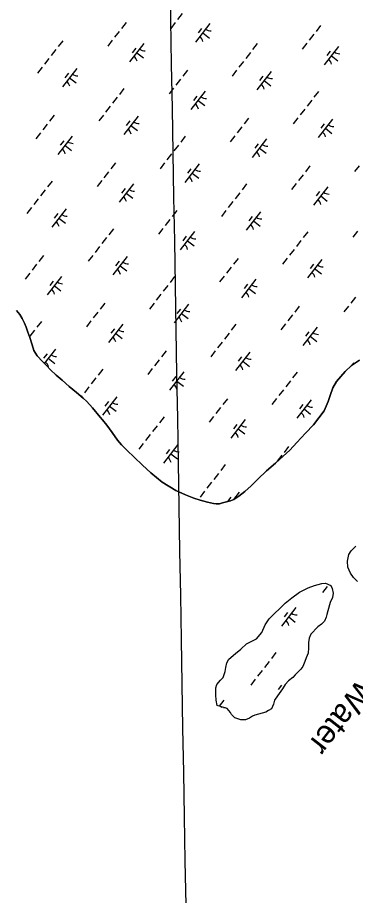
# Model space of a CAD drawing. Extents: x 3888273 to 3909528, y 158682 to 181032.
# Drawn here: x 3904160 to 3904884, y 170026 to 171905 of the extents above; entities that cross this region are included whole.
import ezdxf

# ---------------------------------------------------------------- set-up
doc = ezdxf.new("R2010")
doc.units = 0
for name, color, linetype in [('V-GRID-MAJR', 7, 'Continuous'), ('V-RIVR-IDEN', 7, 'Continuous'), ('V-TOPO-SHOR', 7, 'Continuous'), ('V-WETL-SWMP', 7, 'Continuous')]:
    doc.layers.add(name, color=color, linetype=linetype)

msp = doc.modelspace()

# ---------------------------------------------------------------- linework, layer by layer
at = {"layer": 'V-GRID-MAJR'}
msp.add_spline([(3904558.1, 167799.4), (3904538.3, 168964), (3904435.1, 175024.2), (3904428.3, 175428.5)], degree=3, dxfattribs=at)
at = {"layer": 'V-TOPO-SHOR'}
for points in [[(3904157.7, 171277.9), (3904164.6, 171269.2), (3904169.4, 171261), (3904174.7, 171250.7), (3904178, 171242.4), (3904181.7, 171231.3), (3904185.7, 171219.8), (3904190.7, 171204.8), (3904194.8, 171192.1), (3904202, 171181.1), (3904212.9, 171168.9), (3904222.1, 171159.4), (3904230.2, 171151.2), (3904242.6, 171139.8)], [(3904242.6, 171139.8), (3904255.4, 171128.8), (3904270.3, 171115.4), (3904285.9, 171102.5), (3904299.9, 171090.3), (3904307.9, 171082.9), (3904320, 171069.5), (3904336.9, 171049.8), (3904341.7, 171043.9), (3904350.6, 171032.9), (3904362.3, 171017.1), (3904373.6, 171000.5), (3904382.4, 170990.7), (3904394.8, 170978.1), (3904409.7, 170964), (3904427, 170947.1), (3904445.4, 170930.6), (3904469.8, 170911), (3904498.6, 170892.6), (3904519.4, 170883.7), (3904537.3, 170876.7), (3904550.5, 170872.1), (3904566.4, 170867.9), (3904579.2, 170864.8), (3904585.1, 170864.1), (3904592.3, 170864.6), (3904598.6, 170866.2), (3904607.3, 170868.7), (3904615.6, 170870.8), (3904623.2, 170873.6), (3904633.4, 170880.5), (3904646.4, 170890.6), (3904660.2, 170902.6), (3904674.7, 170917.1), (3904692.8, 170934.8), (3904712.1, 170951.6), (3904728.7, 170966.1), (3904742.8, 170979), (3904757.7, 170995.4), (3904776.6, 171015.5), (3904793.5, 171033.5), (3904805.3, 171048), (3904816.2, 171063.2), (3904825.1, 171083.5), (3904829.4, 171095.9), (3904834.8, 171112.6), (3904843, 171126.2), (3904861.4, 171147.1), (3904875.2, 171160.3), (3904892.1, 171172)], [(3904887.6, 170698.3), (3904879.2, 170707), (3904872.7, 170716), (3904867.1, 170729), (3904866.5, 170741.7), (3904869.6, 170755.6), (3904874.6, 170763.5), (3904884, 170773.9)], [(3904829.1, 170652.9), (3904824.5, 170635.2), (3904822.2, 170627.5), (3904820.8, 170621.8), (3904817.1, 170613.6), (3904810.4, 170606.8), (3904802.9, 170601), (3904787.7, 170585.6), (3904784, 170577), (3904782.7, 170567.9), (3904782.7, 170561.2), (3904782.8, 170556.4), (3904782, 170544.9), (3904778.2, 170534.9), (3904775, 170527.2), (3904770.8, 170516.6), (3904766.6, 170510.9), (3904762.3, 170506.1), (3904754.7, 170498.3), (3904749.1, 170493), (3904740.1, 170485.3), (3904733, 170478), (3904726.9, 170468.4), (3904716.5, 170453.5), (3904710.4, 170443.9), (3904708.1, 170435.8), (3904703.5, 170425.7), (3904697.3, 170421.8), (3904691.6, 170418.4), (3904683.5, 170416.4), (3904675.9, 170414.4), (3904668.3, 170411.9), (3904663, 170410), (3904656.4, 170405.6), (3904648.3, 170402.2), (3904637.8, 170402.1), (3904633.5, 170403.5), (3904625.3, 170406.7), (3904618.1, 170413.3), (3904616.1, 170417.6), (3904608.4, 170426.6), (3904596.4, 170429.8), (3904587.3, 170432.6), (3904585.3, 170444), (3904584.7, 170456), (3904584.1, 170470.8), (3904586.4, 170477.5), (3904594.4, 170487.1), (3904600.1, 170492.9), (3904604.7, 170505.4), (3904605.6, 170514), (3904607.9, 170524), (3904612.1, 170532.2), (3904626.8, 170544.3), (3904638.1, 170553.5), (3904649.9, 170565), (3904661.3, 170570.4), (3904671.8, 170575.8), (3904683.1, 170588.8), (3904690.1, 170605.1), (3904699, 170618.6), (3904733.1, 170651.9), (3904747.3, 170663), (3904763.4, 170675.1), (3904782.4, 170684.9), (3904795.7, 170689.8), (3904811.4, 170693.8), (3904819.6, 170694.3), (3904831.1, 170689.7), (3904833.5, 170683.5), (3904836, 170673), (3904834.2, 170663.9), (3904829.1, 170652.9)]]:
    msp.add_lwpolyline(points, dxfattribs=at)
at = {"layer": 'V-WETL-SWMP'}
for p, q in [((3904512.4, 171913.1), (3904502.5, 171900.5)), ((3904392.2, 171893.9), (3904382.3, 171881.3)), ((3904497.6, 171894.2), (3904487.8, 171881.5)), ((3904377.4, 171875), (3904367.6, 171862.4)), ((3904571.8, 171891.7), (3904541.1, 171852.2)), ((3904554, 171881.4), (3904546.6, 171872)), ((3904808.8, 171887.7), (3904799, 171875.1)), ((3904256.4, 171855.1), (3904246.6, 171842.4)), ((3904362.7, 171856), (3904352.9, 171843.4)), ((3904556.4, 171872), (3904570.6, 171860.9)), ((3904794.1, 171868.8), (3904784.3, 171856.1)), ((3904241.7, 171836.1), (3904231.9, 171823.5)), ((3904430.5, 171849.2), (3904399.8, 171809.8)), ((3904412.8, 171839), (3904405.4, 171829.5)), ((3904673.1, 171848.8), (3904663.3, 171836.2)), ((3904779.3, 171849.8), (3904769.5, 171837.2)), ((3904847.2, 171843), (3904816.5, 171803.6)), ((3904227, 171817.2), (3904217.1, 171804.6)), ((3904415.2, 171829.5), (3904429.4, 171818.5)), ((3904658.4, 171829.9), (3904648.6, 171817.3)), ((3904829.4, 171832.8), (3904822.1, 171823.3)), ((3904831.8, 171823.3), (3904846, 171812.2)), ((3904643.6, 171811), (3904633.8, 171798.3)), ((3904212.2, 171798.2), (3904202.4, 171785.6)), ((3904286.4, 171795.8), (3904255.7, 171756.3)), ((3904268.6, 171785.5), (3904261.2, 171776)), ((3904523.4, 171791.8), (3904513.6, 171779.1)), ((3904628.9, 171792), (3904619.1, 171779.4)), ((3904703, 171789.5), (3904672.3, 171750.1)), ((3904271, 171776), (3904285.2, 171765)), ((3904508.7, 171772.8), (3904498.9, 171760.2)), ((3904685.3, 171779.3), (3904677.9, 171769.8)), ((3904687.7, 171769.8), (3904701.9, 171758.8)), ((3904387.7, 171752.9), (3904377.9, 171740.3)), ((3904494, 171753.9), (3904484.1, 171741.3)), ((3904561.8, 171747.1), (3904531.1, 171707.6)), ((3904804.4, 171746.7), (3904794.6, 171734.1)), ((3904373, 171734), (3904363.2, 171721.4)), ((3904544, 171736.8), (3904536.7, 171727.4)), ((3904546.4, 171727.4), (3904560.7, 171716.3)), ((3904789.7, 171727.8), (3904779.8, 171715.1)), ((3904358.3, 171715), (3904348.4, 171702.4)), ((3904774.9, 171708.8), (3904765.1, 171696.2)), ((3904238.1, 171695.9), (3904228.2, 171683.2)), ((3904343.5, 171696.1), (3904333.7, 171683.5)), ((3904417.7, 171693.6), (3904387, 171654.2)), ((3904654.7, 171689.6), (3904644.9, 171677)), ((3904760.2, 171689.9), (3904750.4, 171677.2)), ((3904834.3, 171687.4), (3904803.6, 171647.9)), ((3904223.3, 171676.9), (3904213.5, 171664.3)), ((3904399.9, 171683.4), (3904392.5, 171673.9)), ((3904402.3, 171673.9), (3904416.5, 171662.8)), ((3904640, 171670.7), (3904630.2, 171658.1)), ((3904816.6, 171677.1), (3904809.2, 171667.7)), ((3904819, 171667.7), (3904833.2, 171656.6)), ((3904208.6, 171658), (3904198.7, 171645.3)), ((3904276.4, 171651.2), (3904245.7, 171611.7)), ((3904519, 171650.8), (3904509.2, 171638.2)), ((3904625.2, 171651.7), (3904615.4, 171639.1)), ((3904258.7, 171640.9), (3904251.3, 171631.5)), ((3904261.1, 171631.4), (3904275.3, 171620.4)), ((3904504.3, 171631.8), (3904494.4, 171619.2)), ((3904693.1, 171645), (3904662.4, 171605.5)), ((3904675.3, 171634.7), (3904668, 171625.2)), ((3904489.5, 171612.9), (3904479.7, 171600.3)), ((3904677.7, 171625.2), (3904691.9, 171614.2)), ((3904369.3, 171593.7), (3904359.5, 171581.1)), ((3904474.8, 171594), (3904465, 171581.3)), ((3904354.6, 171574.8), (3904344.8, 171562.1)), ((3904548.9, 171591.5), (3904518.2, 171552)), ((3904531.2, 171581.2), (3904523.8, 171571.8)), ((3904786, 171587.5), (3904776.2, 171574.9)), ((3904891.5, 171587.7), (3904881.6, 171575.1)), ((3904233.6, 171554.9), (3904223.8, 171542.2)), ((3904339.9, 171555.8), (3904330, 171543.2)), ((3904533.6, 171571.8), (3904547.8, 171560.7)), ((3904771.3, 171568.5), (3904761.4, 171555.9)), ((3904218.9, 171535.9), (3904209.1, 171523.3)), ((3904407.7, 171549), (3904377, 171509.6)), ((3904389.9, 171538.8), (3904382.6, 171529.3)), ((3904650.3, 171548.6), (3904640.5, 171536)), ((3904756.5, 171549.6), (3904746.7, 171537)), ((3904824.4, 171542.8), (3904793.7, 171503.3)), ((3904204.1, 171517), (3904194.3, 171504.4)), ((3904392.3, 171529.3), (3904406.5, 171518.2)), ((3904635.6, 171529.7), (3904625.7, 171517.1)), ((3904806.6, 171532.6), (3904799.2, 171523.1)), ((3904809, 171523.1), (3904823.2, 171512)), ((3904189.4, 171498), (3904179.6, 171485.4)), ((3904620.8, 171510.8), (3904611, 171498.1)), ((3904263.5, 171495.6), (3904232.8, 171456.1)), ((3904245.8, 171485.3), (3904238.4, 171475.8)), ((3904500.6, 171491.6), (3904490.8, 171478.9)), ((3904606.1, 171491.8), (3904596.2, 171479.2)), ((3904680.2, 171489.3), (3904649.5, 171449.9)), ((3904248.2, 171475.8), (3904262.4, 171464.8)), ((3904485.9, 171472.6), (3904476, 171460)), ((3904662.5, 171479.1), (3904655.1, 171469.6)), ((3904664.9, 171469.6), (3904679.1, 171458.6)), ((3904364.9, 171452.7), (3904355.1, 171440.1)), ((3904471.1, 171453.7), (3904461.3, 171441.1)), ((3904539, 171446.9), (3904508.3, 171407.4)), ((3904781.6, 171446.5), (3904771.7, 171433.9)), ((3904887.8, 171447.5), (3904878, 171434.8)), ((3904350.2, 171433.8), (3904340.3, 171421.1)), ((3904521.2, 171436.6), (3904513.9, 171427.2)), ((3904523.6, 171427.2), (3904537.8, 171416.1)), ((3904766.8, 171427.6), (3904757, 171414.9)), ((3904335.4, 171414.8), (3904325.6, 171402.2)), ((3904752.1, 171408.6), (3904742.3, 171396)), ((3904215.2, 171395.7), (3904205.4, 171383)), ((3904320.7, 171395.9), (3904310.9, 171383.3)), ((3904394.8, 171393.4), (3904364.1, 171354)), ((3904631.9, 171389.4), (3904622.1, 171376.8)), ((3904737.4, 171389.7), (3904727.5, 171377)), ((3904811.5, 171387.2), (3904780.8, 171347.7)), ((3904200.5, 171376.7), (3904190.7, 171364.1)), ((3904377.1, 171383.2), (3904369.7, 171373.7)), ((3904379.5, 171373.7), (3904393.7, 171362.6)), ((3904617.2, 171370.5), (3904607.3, 171357.9)), ((3904793.7, 171376.9), (3904786.4, 171367.5)), ((3904796.1, 171367.5), (3904810.4, 171356.4)), ((3904185.7, 171357.8), (3904175.9, 171345.1)), ((3904253.6, 171351), (3904222.9, 171311.5)), ((3904496.2, 171350.6), (3904486.4, 171337.9)), ((3904602.4, 171351.5), (3904592.6, 171338.9)), ((3904235.8, 171340.7), (3904228.5, 171331.2)), ((3904238.2, 171331.2), (3904252.4, 171320.2)), ((3904481.4, 171331.6), (3904471.6, 171319)), ((3904670.3, 171344.7), (3904639.6, 171305.3)), ((3904652.5, 171334.5), (3904645.1, 171325)), ((3904466.7, 171312.7), (3904456.9, 171300.1)), ((3904654.9, 171325), (3904669.1, 171314)), ((3904346.5, 171293.5), (3904336.7, 171280.9)), ((3904452, 171293.7), (3904442.1, 171281.1)), ((3904883.4, 171306.5), (3904873.5, 171293.8)), ((3904164.6, 171269.2), (3904157.7, 171277.9)), ((3904331.8, 171274.6), (3904321.9, 171261.9)), ((3904526.1, 171291.3), (3904495.4, 171251.8)), ((3904508.4, 171281), (3904501, 171271.5)), ((3904763.2, 171287.3), (3904753.3, 171274.7)), ((3904868.6, 171287.5), (3904858.8, 171274.9)), ((3904169.4, 171261), (3904164.6, 171269.2)), ((3904174.7, 171250.7), (3904169.4, 171261)), ((3904210.8, 171254.7), (3904201, 171242)), ((3904317, 171255.6), (3904307.2, 171243)), ((3904510.8, 171271.5), (3904525, 171260.5)), ((3904748.4, 171268.3), (3904738.6, 171255.7)), ((3904178, 171242.4), (3904174.7, 171250.7)), ((3904181.7, 171231.3), (3904178, 171242.4)), ((3904196.1, 171235.7), (3904186.2, 171223.1)), ((3904384.9, 171248.8), (3904354.2, 171209.4)), ((3904367.1, 171238.6), (3904359.7, 171229.1)), ((3904627.5, 171248.4), (3904617.6, 171235.8)), ((3904733.7, 171249.4), (3904723.9, 171236.8)), ((3904801.5, 171242.6), (3904770.8, 171203.1)), ((3904185.7, 171219.8), (3904181.7, 171231.3)), ((3904190.7, 171204.8), (3904185.7, 171219.8)), ((3904369.5, 171229.1), (3904383.7, 171218)), ((3904612.7, 171229.5), (3904602.9, 171216.9)), ((3904783.8, 171232.3), (3904776.4, 171222.9)), ((3904786.2, 171222.9), (3904800.4, 171211.8)), ((3904194.8, 171192.1), (3904190.7, 171204.8)), ((3904598, 171210.5), (3904588.2, 171197.9)), ((3904202, 171181.1), (3904194.8, 171192.1)), ((3904212.9, 171168.9), (3904202, 171181.1)), ((3904223, 171185.1), (3904215.6, 171175.6)), ((3904240.7, 171195.4), (3904216.9, 171164.8)), ((3904477.8, 171191.4), (3904468, 171178.7)), ((3904583.2, 171191.6), (3904573.4, 171179)), ((3904657.4, 171189.1), (3904626.7, 171149.7)), ((3904639.6, 171178.9), (3904632.3, 171169.4)), ((3904222.1, 171159.4), (3904212.9, 171168.9)), ((3904225.4, 171175.6), (3904239.6, 171164.6)), ((3904463, 171172.4), (3904453.2, 171159.8)), ((3904642, 171169.4), (3904656.2, 171158.3)), ((3904875.2, 171160.3), (3904861.4, 171147.1)), ((3904879.7, 171166.2), (3904875, 171160.1)), ((3904892.1, 171172), (3904875.2, 171160.3)), ((3904230.2, 171151.2), (3904222.1, 171159.4)), ((3904242.6, 171139.8), (3904230.2, 171151.2)), ((3904342.1, 171152.5), (3904332.3, 171139.9)), ((3904448.3, 171153.5), (3904438.5, 171140.8)), ((3904516.2, 171146.7), (3904485.4, 171107.2)), ((3904758.7, 171146.3), (3904748.9, 171133.7)), ((3904861.4, 171147.1), (3904843, 171126.2)), ((3904255.4, 171128.8), (3904242.6, 171139.8)), ((3904270.3, 171115.4), (3904255.4, 171128.8)), ((3904327.3, 171133.6), (3904317.5, 171120.9)), ((3904498.4, 171136.4), (3904491, 171127)), ((3904500.8, 171127), (3904515, 171115.9)), ((3904744, 171127.3), (3904734.2, 171114.7)), ((3904843, 171126.2), (3904834.8, 171112.6)), ((3904285.9, 171102.5), (3904270.3, 171115.4)), ((3904312.6, 171114.6), (3904302.8, 171102)), ((3904729.3, 171108.4), (3904719.4, 171095.8)), ((3904834.8, 171112.6), (3904829.4, 171095.9)), ((3904299.9, 171090.3), (3904285.9, 171102.5)), ((3904297.9, 171095.7), (3904296.2, 171093.5)), ((3904307.9, 171082.9), (3904299.9, 171090.3)), ((3904372, 171093.2), (3904341.3, 171053.7)), ((3904609.1, 171089.2), (3904599.2, 171076.6)), ((3904714.5, 171089.5), (3904704.7, 171076.8)), ((3904788.7, 171087), (3904758, 171047.5)), ((3904829.4, 171095.9), (3904825.1, 171083.5)), ((3904320, 171069.5), (3904307.9, 171082.9)), ((3904336.9, 171049.8), (3904320, 171069.5)), ((3904354.2, 171083), (3904346.9, 171073.5)), ((3904356.7, 171073.5), (3904370.9, 171062.4)), ((3904594.3, 171070.3), (3904584.5, 171057.6)), ((3904770.9, 171076.7), (3904763.5, 171067.3)), ((3904773.3, 171067.3), (3904787.5, 171056.2)), ((3904825.1, 171083.5), (3904816.2, 171063.2)), ((3904341.7, 171043.9), (3904336.9, 171049.8)), ((3904473.4, 171050.4), (3904463.5, 171037.7)), ((3904579.6, 171051.3), (3904569.8, 171038.7)), ((3904805.3, 171048), (3904793.5, 171033.5)), ((3904816.2, 171063.2), (3904805.3, 171048)), ((3904350.6, 171032.9), (3904341.7, 171043.9)), ((3904362.3, 171017.1), (3904350.6, 171032.9)), ((3904458.6, 171031.4), (3904448.8, 171018.8)), ((3904647.4, 171044.5), (3904616.7, 171005.1)), ((3904629.7, 171034.3), (3904622.3, 171024.8)), ((3904793.5, 171033.5), (3904776.6, 171015.5)), ((3904373.6, 171000.5), (3904362.3, 171017.1)), ((3904443.9, 171012.5), (3904434.1, 170999.9)), ((3904632.1, 171024.8), (3904646.3, 171013.8)), ((3904776.6, 171015.5), (3904757.7, 170995.4)), ((3904382.4, 170990.7), (3904373.6, 171000.5)), ((3904429.1, 170993.5), (3904419.3, 170980.9)), ((3904503.3, 170991.1), (3904472.6, 170951.6)), ((3904757.7, 170995.4), (3904742.8, 170979)), ((3904394.8, 170978.1), (3904382.4, 170990.7)), ((3904409.7, 170964), (3904394.8, 170978.1)), ((3904485.5, 170980.8), (3904478.2, 170971.3)), ((3904742.8, 170979), (3904728.7, 170966.1)), ((3904740.3, 170987.1), (3904730.5, 170974.4)), ((3904427, 170947.1), (3904409.7, 170964)), ((3904487.9, 170971.3), (3904502.1, 170960.3)), ((3904728.7, 170966.1), (3904712.1, 170951.6)), ((3904725.6, 170968.1), (3904715.8, 170955.5)), ((3904445.4, 170930.6), (3904427, 170947.1)), ((3904604.6, 170948.2), (3904594.8, 170935.6)), ((3904692.8, 170934.8), (3904674.7, 170917.1)), ((3904712.1, 170951.6), (3904692.8, 170934.8)), ((3904469.8, 170911), (3904445.4, 170930.6)), ((3904589.9, 170929.3), (3904580.1, 170916.7)), ((3904674.7, 170917.1), (3904660.2, 170902.6)), ((3904498.6, 170892.6), (3904469.8, 170911)), ((3904575.2, 170910.3), (3904565.3, 170897.7)), ((3904660.2, 170902.6), (3904646.4, 170890.6)), ((3904519.4, 170883.7), (3904498.6, 170892.6)), ((3904537.3, 170876.7), (3904519.4, 170883.7)), ((3904560.4, 170891.4), (3904550.6, 170878.8)), ((3904616.8, 170878.7), (3904609.5, 170869.2)), ((3904634.6, 170888.9), (3904622.5, 170873.4)), ((3904633.4, 170880.5), (3904623.2, 170873.6)), ((3904646.4, 170890.6), (3904633.4, 170880.5)), ((3904550.5, 170872.1), (3904537.3, 170876.7)), ((3904566.4, 170867.9), (3904550.5, 170872.1)), ((3904579.2, 170864.8), (3904566.4, 170867.9)), ((3904585.1, 170864.1), (3904579.2, 170864.8)), ((3904592.3, 170864.6), (3904585.1, 170864.1)), ((3904598.6, 170866.2), (3904592.3, 170864.6)), ((3904607.3, 170868.7), (3904598.6, 170866.2)), ((3904615.6, 170870.8), (3904607.3, 170868.7)), ((3904623.2, 170873.6), (3904615.6, 170870.8)), ((3904874.6, 170763.5), (3904884, 170773.9)), ((3904866.5, 170741.7), (3904869.6, 170755.6)), ((3904869.6, 170755.6), (3904874.6, 170763.5)), ((3904867.1, 170729), (3904866.5, 170741.7)), ((3904867.2, 170743.9), (3904867, 170743.6)), ((3904872.7, 170716), (3904867.1, 170729)), ((3904879.2, 170707), (3904872.7, 170716)), ((3904887.6, 170698.3), (3904879.2, 170707)), ((3904823, 170687.1), (3904813.2, 170674.5)), ((3904755.9, 170642.2), (3904725.2, 170602.7)), ((3904738.1, 170631.9), (3904730.8, 170622.5)), ((3904740.5, 170622.5), (3904754.7, 170611.4)), ((3904713.1, 170545.9), (3904703.3, 170533.2)), ((3904698.4, 170526.9), (3904688.5, 170514.3)), ((3904683.6, 170508), (3904673.8, 170495.4)), ((3904668.9, 170489), (3904659.1, 170476.4)), ((3904725.3, 170476.3), (3904717.9, 170466.8)), ((3904713.1, 170448.1), (3904712.3, 170447.1)), ((3904601.8, 170444.1), (3904591.8, 170431.2))]:
    msp.add_line(p, q, dxfattribs=at)
msp.add_lwpolyline([(3904829.1, 170652.9), (3904824.5, 170635.2), (3904822.2, 170627.5), (3904820.8, 170621.8), (3904817.1, 170613.6), (3904810.4, 170606.8), (3904802.9, 170601), (3904787.7, 170585.6), (3904784, 170577), (3904782.7, 170567.9), (3904782.7, 170561.2), (3904782.8, 170556.4), (3904782, 170544.9), (3904778.2, 170534.9), (3904775, 170527.2), (3904770.8, 170516.6), (3904766.6, 170510.9), (3904762.3, 170506.1), (3904754.7, 170498.3), (3904749.1, 170493), (3904740.1, 170485.3), (3904733, 170478), (3904726.9, 170468.4), (3904716.5, 170453.5), (3904710.4, 170443.9), (3904708.1, 170435.8), (3904703.5, 170425.7), (3904697.3, 170421.8), (3904691.6, 170418.4), (3904683.5, 170416.4), (3904675.9, 170414.4), (3904668.3, 170411.9), (3904663, 170410), (3904656.4, 170405.6), (3904648.3, 170402.2), (3904637.8, 170402.1), (3904633.5, 170403.5), (3904625.3, 170406.7), (3904618.1, 170413.3), (3904616.1, 170417.6), (3904608.4, 170426.6), (3904596.4, 170429.8), (3904587.3, 170432.6), (3904585.3, 170444), (3904584.7, 170456), (3904584.1, 170470.8), (3904586.4, 170477.5), (3904594.4, 170487.1), (3904600.1, 170492.9), (3904604.7, 170505.4), (3904605.6, 170514), (3904607.9, 170524), (3904612.1, 170532.2), (3904626.8, 170544.3), (3904638.1, 170553.5), (3904649.9, 170565), (3904661.3, 170570.4), (3904671.8, 170575.8), (3904683.1, 170588.8), (3904690.1, 170605.1), (3904699, 170618.6), (3904733.1, 170651.9), (3904747.3, 170663), (3904763.4, 170675.1), (3904782.4, 170684.9), (3904795.7, 170689.8), (3904811.4, 170693.8), (3904819.6, 170694.3), (3904831.1, 170689.7), (3904833.5, 170683.5), (3904836, 170673), (3904834.2, 170663.9)], close=True, dxfattribs=at)
for centre, start, end in [((3904573.6, 171893.6), 231.343, 272.8866), ((3904539.6, 171850), 11.343, 52.8866), ((3904432.3, 171851.2), 231.343, 272.8866), ((3904398.4, 171807.6), 11.343, 52.8866), ((3904849, 171844.9), 231.343, 272.8866), ((3904815.1, 171801.3), 11.343, 52.8866), ((3904288.2, 171797.7), 231.343, 272.8866), ((3904254.2, 171754.1), 11.343, 52.8866), ((3904670.9, 171747.9), 11.343, 52.8866), ((3904704.8, 171791.5), 231.343, 272.8866), ((3904563.6, 171749), 231.343, 272.8866), ((3904529.7, 171705.4), 11.343, 52.8866), ((3904419.5, 171695.6), 231.343, 272.8866), ((3904836.1, 171689.3), 231.343, 272.8866), ((3904385.5, 171652), 11.343, 52.8866), ((3904802.2, 171645.7), 11.343, 52.8866), ((3904278.2, 171653.1), 231.343, 272.8866), ((3904694.9, 171646.9), 231.343, 272.8866), ((3904244.3, 171609.5), 11.343, 52.8866), ((3904661, 171603.3), 11.343, 52.8866), ((3904550.7, 171593.4), 231.343, 272.8866), ((3904516.8, 171549.8), 11.343, 52.8866), ((3904409.5, 171551), 231.343, 272.8866), ((3904375.6, 171507.4), 11.343, 52.8866), ((3904826.2, 171544.7), 231.343, 272.8866), ((3904792.2, 171501.1), 11.343, 52.8866), ((3904265.3, 171497.5), 231.343, 272.8866), ((3904231.4, 171453.9), 11.343, 52.8866), ((3904648.1, 171447.7), 11.343, 52.8866), ((3904682, 171491.3), 231.343, 272.8866), ((3904540.8, 171448.8), 231.343, 272.8866), ((3904506.8, 171405.2), 11.343, 52.8866), ((3904396.6, 171395.3), 231.343, 272.8866), ((3904813.3, 171389.1), 231.343, 272.8866), ((3904362.7, 171351.7), 11.343, 52.8866), ((3904779.4, 171345.5), 11.343, 52.8866), ((3904255.4, 171352.9), 231.343, 272.8866), ((3904672.1, 171346.7), 231.343, 272.8866), ((3904221.5, 171309.3), 11.343, 52.8866), ((3904638.1, 171303.1), 11.343, 52.8866), ((3904527.9, 171293.2), 231.343, 272.8866), ((3904494, 171249.6), 11.343, 52.8866), ((3904386.7, 171250.7), 231.343, 272.8866), ((3904352.7, 171207.1), 11.343, 52.8866), ((3904803.3, 171244.5), 231.343, 272.8866), ((3904769.4, 171200.9), 11.343, 52.8866), ((3904242.5, 171197.3), 231.343, 272.8866), ((3904208.6, 171153.7), 11.343, 52.8866), ((3904625.3, 171147.5), 11.343, 52.8866), ((3904659.2, 171191.1), 231.343, 272.8866), ((3904517.9, 171148.6), 231.343, 272.8866), ((3904484, 171105), 11.343, 52.8866), ((3904373.8, 171095.1), 231.343, 272.8866), ((3904790.5, 171088.9), 231.343, 272.8866), ((3904339.9, 171051.5), 11.343, 52.8866), ((3904756.5, 171045.3), 11.343, 52.8866), ((3904649.2, 171046.5), 231.343, 272.8866), ((3904615.3, 171002.9), 11.343, 52.8866), ((3904505.1, 170993), 231.343, 272.8866), ((3904471.2, 170949.4), 11.343, 52.8866), ((3904636.4, 170890.8), 231.343, 237.0562), ((3904757.7, 170644.1), 231.343, 272.8866), ((3904723.8, 170600.5), 11.343, 52.8866), ((3904603.6, 170446), 231.343, 249.1013), ((3904603.6, 170446), 260.8108, 272.8866)]:
    msp.add_arc(centre, 17.6, start, end, dxfattribs=at)

# ---------------------------------------------------------------- texts
at = {"layer": 'V-RIVR-IDEN'}
msp.add_text('Water', height=50, rotation=232.1185, dxfattribs=at).set_placement((3904890, 170491.9))

doc.saveas('drawing.dxf')
